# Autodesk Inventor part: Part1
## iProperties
Shininess: 64.0
Length Units: 11269
Angle Units: 11279
Time Units: 11290
Mass Units: 11283
Length Display Precision: 3
Angle Display Precision: 2
Compacted: True
Part Number: Part1
Document SubType Name: Modeling
Created: 2002-12
Designer: deepak
Density: 0.0
Volumn: 0.0
Area: 0.0
PropertySet Name: Model Information
Control State: 0
Master: False
Checked Out: False
Author: deepak
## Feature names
1. Revolution1
